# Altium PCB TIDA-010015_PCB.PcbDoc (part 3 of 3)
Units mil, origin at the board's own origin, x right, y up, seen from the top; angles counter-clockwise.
Board outline 6299.21 x 3149.61 mil, 2 copper layers (Top Layer, Bottom Layer), stack 64.6 mil thick; 232 components, 110 nets, 524 pads, 83 vias.
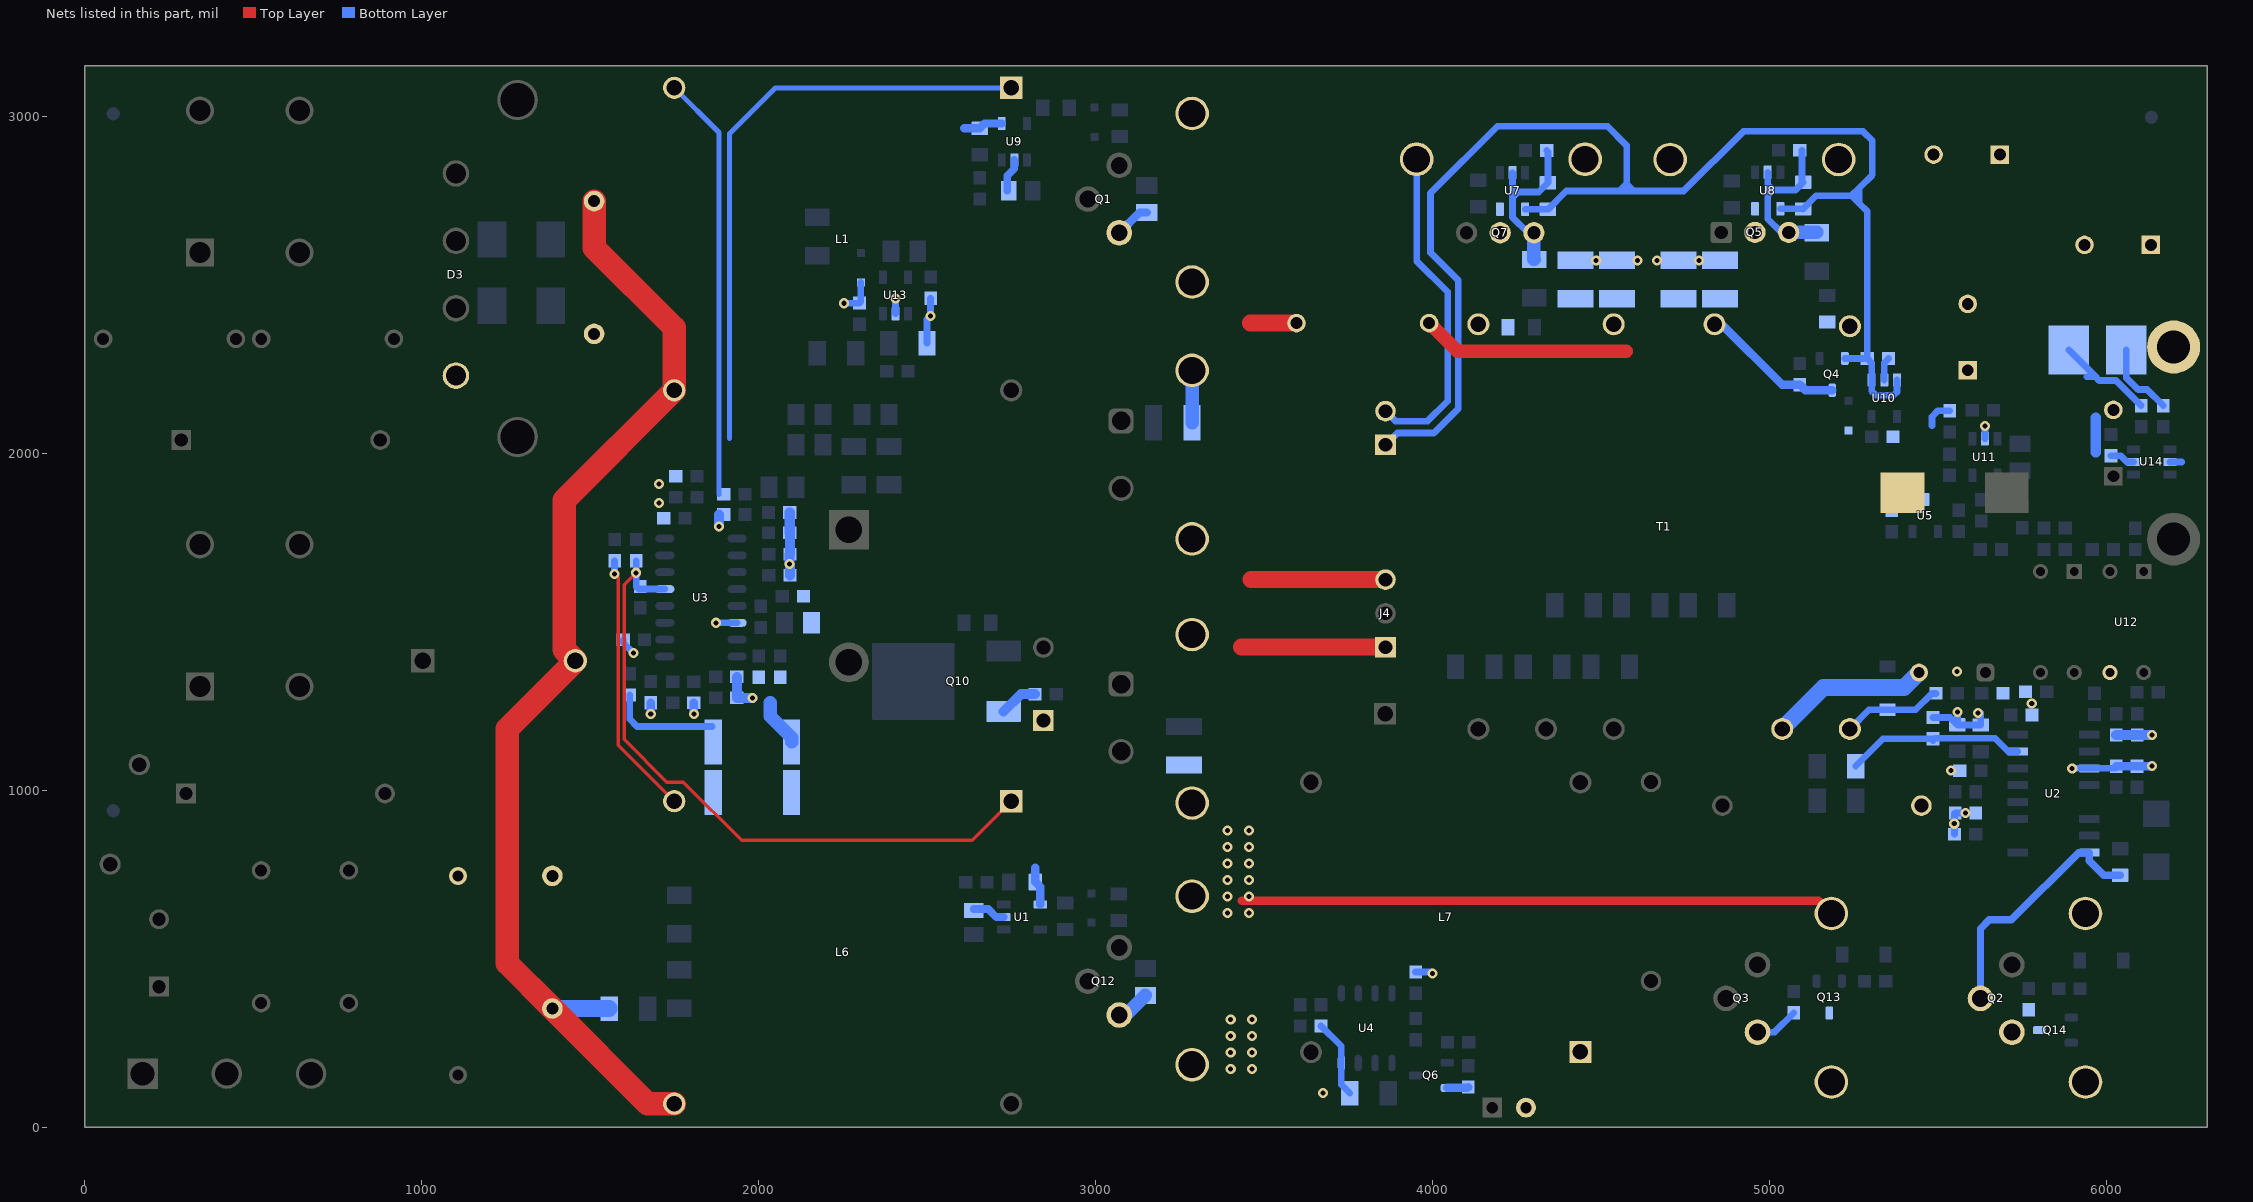
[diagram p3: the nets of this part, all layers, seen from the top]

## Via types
v1: diameter 30, hole 15, Top Layer to Bottom Layer, 83 vias

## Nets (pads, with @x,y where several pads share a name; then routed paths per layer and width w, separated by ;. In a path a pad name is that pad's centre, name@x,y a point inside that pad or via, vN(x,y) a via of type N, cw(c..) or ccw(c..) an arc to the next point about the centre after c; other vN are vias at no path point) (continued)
PGND: C3.2 C7.2 C8.2 C15.1 C16.2 C17.2 C18.2 C19.2 C20.2 C21.2 C22.2 C23.2 C24.2 C25.2 C27.2 C28.2 C29.2 C30.1 C31.2 C32.2 C33.2 C34.2 C35.1 C36.2 C37.2 C38.2 C41.2 C43.2 C51.2 C52.2 C58.2 C59.2 C60.2 C65.2 D20.2 J2.2 J4.1 J4.3 L1.1 L6.1 M1.1 M1.2 M2.1 M2.2 M3.1 M3.2 M4.1 M4.2 M5.1 M5.2 M6.1 M6.2 Q1.3 Q2.3 Q6.2 Q10.3 Q12.3 Q14.3 R1.1 R2.1 R3.1 R6.1 R7.1 R8.1 R11.2 R12.1 R14.2 R19.1 R32.1 R35.1 R41.2 R45.1 R55.1 R64.1 R76.1 R88.2 R89.1 R90.1 RF1.1 T1.5 U1.2 U1.4 U2.11 U3.6 U3.13 U4.4 U9.2 U9.4 U12.3 U13.2 | length 9882.2
  Top Layer w10: v1(1636.71,1645) 1601,1609.29 1601,1151 1728.02,1023.98 1777.02,1023.98 1950,851 2633.43,851 L6.1@2749.63,967.2
  Top Layer w25: 3434.29,671.29 5146.01,671.29 M2.1@5183.31,634
  Top Layer w50: 3432.66,1424.66 J4.1@3860.25,1424.66 ; 3459,2386 C8.2@3596.15,2386 ; 3461.66,1624.66 J4.3@3860.25,1624.66
  Bottom Layer w15: 1914.3,2043.3 1914.3,2948.3 2050.2,3084.2 L1.1@2749.63,3084.2
  Bottom Layer w20: C29.2@1598.5,1446 1598.5,1437.5 v1(1629,1407) ; C24.2@1636.79,1680.78 1636.71,1680.7 v1(1636.71,1645) 1636.71,1604.5 1644.5,1596.7 U3.13@1721.71,1596.7 ; v1(1873.99,1496.7) U3.6@1936.28,1496.7 ; v1(2253,2444.91) 2298.97,2444.91 C28.2@2299.42,2445.36 2303.42,2449.36 D20.2@2303.42,2506.69 ; U13.2@2406.42,2413.87 v1(2406.42,2459.5) ; R76.1@2500.09,2325.91 2500.09,2397.17 v1(2510.42,2407.5) C27.2@2510.42,2459.5 ; R55.1@3669,300.5 3729.36,240.14 U4.4@3729.36,190.49 3729.36,125.75 C51.2@3754.28,100.84 ; C52.2@3949.49,460.18 3995.82,460.18 v1(4000,456) ; C22.2@5485,1215.5 5535.74,1215.5 C19.2@5557.41,1193.83 ; C16.2@5548.5,869 5548.5,930.54 C17.2@5550.47,932.5 v1(5581.91,932.5) ; v1(5557.69,1232) 5557.41,1231.72 C19.2@5557.41,1193.83 ; v1(5619,1229) 5626.16,1229 5626.41,1228.75 R3.1@5626.41,1193.1 5558.13,1193.1 C19.2@5557.41,1193.83 ; v1(5898,1064.85) U2.11@5948.77,1064.85 6026.06,1064.85 C32.2@6032.56,1071.34
  Bottom Layer w23: C23.2@2638.66,647.4 2681.66,647.4 2705.66,623.4 U1.2@2727.73,623.4 ; C15.1@2738,2779 2738,2823 2759,2844 U9.2@2759,2869.87
  Bottom Layer w25: v1(1680,1225.67) C37.2@1679.99,1259.51 ; v1(1808,1225.66) R11.2@1807.99,1259.5 ; 2609.85,2963.85 C59.2@2656,2963.85 2670.28,2978.13 U9.4@2721.6,2978.13 ; 2821.24,769.4 C58.2@2821.24,727.4 2836,712.64 U1.4@2836,660.8 ; Q1.3@3070.17,2654.01 3130.23,2714.07 R6.1@3152,2714.07 ; Q6.2@4043.76,116.39 4103.39,116.39 R64.1@4106,119 ; C32.2@6028.47,1071.34 6032.56,1071.34 v1(6134.47,1071.34)
  Bottom Layer w30: v1(1882.5,1781.99) C25.2@1882.5,1818 ; R88.2@1935.51,1336 C41.2@1935.51,1274 v1(1981.88,1274) ; R35.1@2092.44,1824.04 C33.2@2092.44,1764.04 2092.99,1763.48 R89.1@2092.99,1700.5 2092,1699.51 v1(2092,1671) 2092.99,1670.01 C21.2@2092.99,1637.5 ; Q10.3@2726.86,1233.24 2778.62,1285 R14.2@2820.5,1285 ; R32.1@6028.47,1163.85 C31.2@6090.47,1163.85 6133.97,1163.85 v1(6134.47,1163.34)
  Bottom Layer w40: 2035,1260 2035,1219 2098,1156 R7.1@2098,1143.24 ; Q12.3@3070.17,332.93 3089.93,332.93 R19.1@3148,391 ; C7.2@3286.09,2090 3286.47,2090.39 M6.1@3286.47,2245.72
  Bottom Layer w50: T1.5@5037.39,1181.61 5160.29,1304.5 5399.08,1304.5 C60.2@5443.57,1349
  other v1: 3675,101 3401,172.3 3464,172.3 3401,221.3 3464,221.3 3401,270.3 3464,270.3 3401,319.3 3464,319.3 3392,635 3455,635 3392,684 3455,684 3392,733 3455,733 3392,782 3455,782 3392,831 3455,831 3392,880 3455,880 5547.91,900.5 5537.94,1058 5778,1257 5556,1352 1704,1852 1704,1908.16
R_SENSE: pad.1@6199,2315 R65.2 R66.1 | length 226.1
  Bottom Layer w20: R65.2@6058.04,2306 6058.04,2224.64 6093.68,2189 6120.3,2189 R66.1@6168.2,2141.09
SGND: C12.2 C13.2 C14.2 C44.1 C45.1 C46.2 C48.2 C53.2 C54.2 C55.2 C56.2 C57.2 C67.2 C68.2 C72.2 C73.2 C76.2 D4.2 J5.2 M7.1 M7.2 M8.1 M8.2 Q5.3 Q7.3 R50.1 R65.1 R72.1 R78.1 U5.3 U7.2 U8.2 U10.2 U11.2 U14.2 U14.5 | length 2810.5
  Top Layer w20: v1@5638.87,2081 v1(5639,2080.87)
  Bottom Layer w20: J5.2@3860.25,2124.66 3889.91,2095 3984.87,2095 4045,2155.13 4045,2478 3952.86,2570.14 M7.1@3952.86,2872.1 ; U7.2@4237.32,2832.11 4237.32,2792.68 ; Q7.3@4300.7,2654.06 4282.94,2654.06 4237.32,2699.68 4237.32,2758 ; C53.2@4338.81,2897.97 4342.32,2894.47 C46.2@4342.32,2802.34 4314.97,2775 4255,2775 ; U8.2@4994.39,2833.36 4994.39,2798 ; Q5.3@5056.7,2655.06 5034.94,2655.06 4994.39,2695.61 4994.39,2763.72 ; C54.2@5095.88,2899.22 5095.88,2807.1 C48.2@5099.39,2803.59 5076.65,2780.86 5011.53,2780.86 ; U10.2@5340.44,2217.02 5340.44,2268.32 C55.2@5353,2280.89 ; 5482,2081 5482,2108.16 5499.92,2126.08 R72.1@5535,2126.08 ; v1(5639,2080.87) 5639.07,2080.8 U11.2@5639.07,2042.63 ; R65.1@5887.96,2306 5966.98,2226.98 ; 5940.98,2226.98 5966.98,2226.98 ; C57.2@6013,1992.5 6041.5,1992.5 6060,1974 U14.5@6079.73,1974 ; R78.1@6102.41,2141.09 6027.65,2215.86 5978.1,2215.86 5966.98,2226.98 ; U14.2@6188,1974 6188.4,1973.6 6223.39,1973.6 ; 4237.32,2758 4237.32,2775 ; 4237.32,2758 4254.32,2775 ; 4237.32,2775 4254.32,2775 ; 4237.32,2775 4237.32,2792.68 ; 4237.32,2792.68 4255,2775 ; 4254.32,2775 4255,2775 ; 4994.39,2763.72 4994.39,2780.86 ; 4994.39,2763.72 5011.53,2780.86 ; 4994.39,2780.86 5011.53,2780.86 ; 4994.39,2780.86 4994.39,2798 ; 4994.39,2798 5011.53,2780.86
  Bottom Layer w30: 5968,2002 5968,2105
  Bottom Layer w40: Q7.3@4300.7,2654.06 4300.7,2575.76 C45.1@4301.45,2575 ; Q5.3@5056.7,2655.06 C44.1@5139.97,2655.06
  other v1: 4485.5,2572.09 4608,2572 4666,2572 4790,2572.09
SW: C26.2 L7.1 Q2.2 Q3.3 Q13.3 R44.1 U2.16 | length 888.7
  Bottom Layer w20: Q3.3@4964,282 5014.5,282 R44.1@5072,339.5
  Bottom Layer w22: Q2.2@5625.83,382.07 5625.83,589.13 5652,615.3 5717.35,615.3 5916.9,814.85 U2.16@5948.77,814.85 5948.77,790.38 5991.52,747.63 C26.2@6040,747.63
V24V: C8.1 C12.1 C13.1 C14.1 C67.1 C68.1 C72.1 C73.1 L4.1 Q4.3 R62.2 T1.8 T1.9 | length 1049.4
  Top Layer w40: C8.1@3989.85,2386 4073.85,2302 4574,2302
  Bottom Layer w25: T1.8@4836.61,2382.39 4857.61,2382.39 5036.8,2203.2 R62.2@5090,2203.2 5106.45,2186.76 Q4.3@5186,2186.76
VAC: C5.1 C61.1 L1.3 L2.2 L6.3 R23.2 | length 3430.2
  Top Layer w70: C61.1@1512,2747.85 1512,2609.72 1749.63,2372.09 L1.3@1749.63,2186.56 1423,1859.93 1423,1417.38 L2.2@1456.38,1384 1254,1181.62 1254,486.15 C5.1@1388,352.15 1670.59,69.56 L6.3@1749.63,69.56
  Bottom Layer w50: C5.1@1388,352.15 1388.15,352 R23.2@1556.91,352
VCR: C22.1 C40.2 U2.7 | length 533.5
  Bottom Layer w20: C40.2@5255.37,1071 5336.87,1152.5 C22.1@5485,1152.5 ; C22.1@5485,1147.5 5491.5,1154 5668.96,1154 5708.11,1114.85 U2.7@5736.17,1114.85
VD1: Q7.2 R53.1 T1.10 U7.5
VD2: Q5.2 R52.1 T1.7 U8.5
VDD: C46.1 C48.1 C55.1 J5.1 Q4.2 U7.4 U8.4 U10.1 U10.3 | length 4219.1
  Bottom Layer w20: J5.1@3860.25,2024.66 3895.59,2060 4003.82,2060 4076.44,2132.62 4076.44,2512.56 3994,2595 3994,2771.51 4192.49,2970 4519,2970 4576,2913 4576,2799 ; U7.4@4274.72,2723.84 4274.95,2723.6 C46.1@4342.32,2723.6 4396.71,2778 4555,2778 ; 4607,2778 4597,2778 ; U8.4@5031.79,2725.09 5099.15,2725.09 C48.1@5099.39,2724.85 5138.54,2764 5243,2764 ; Q4.2@5223.4,2281.24 5223.76,2280.89 C55.1@5290.01,2280.89 ; 5267.91,2788.91 5266,2787 ; U10.3@5377.84,2217.02 5377.84,2181.67 5368.09,2171.92 5316.09,2171.92 5303.03,2184.97 U10.1@5303.03,2217.02 5303.03,2267.86 C55.1@5290.01,2280.89 ; 4555,2778 4576,2799 ; 4555,2778 4576,2778 ; 4576,2778 4576,2799 ; 4576,2778 4597,2778 ; 4576,2799 4597,2778 ; 4597,2778 4745,2778 4922,2955 5277,2955 5305,2927 5305,2826 5266,2787 ; 5243,2764 5266,2741 ; 5243,2764 5266,2787 ; 5266,2741 5290.01,2716.99 C55.1@5290.01,2280.89 ; 5266,2741 5266,2787
VN: C4.2 C5.2 C61.2 D3.4 R7.2 R8.2 R30.1 | length 324.9
  Bottom Layer w20: R30.1@1618,1282.5 1618,1210.49 1639.49,1189 R7.2@1862,1189
X: D11.2 R9.2 T1.6 | length 299
  Bottom Layer w20: T1.6@5238.18,1181.61 5295.11,1238.53 D11.2@5350,1238.53 5433.53,1238.53 5482,1287 R9.2@5493.5,1287
ZCD1: L1.2 R26.2 | length 1261.2
  Bottom Layer w15: L1.2@1749.63,3084.2 1882.5,2951.33 R26.2@1882.5,1878
ZCD2: L6.2 R24.1 | length 786.7
  Top Layer w10: v1@1572.3,1641.3 1583.3,1630.3 1583.3,1133.53 L6.2@1749.63,967.2
  Bottom Layer w20: v1(1572.68,1641.68) R24.1@1572.68,1680.78
pads on no net: FID1.1 FID2.1 FID3.1 H1.0 H2.0 H3.0 H4.0 H5.0 H6.0 H7.1 H7.2 L7.4 T1.2 U4.2 U4.5 U4.6 U10.4

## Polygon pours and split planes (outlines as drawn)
24V on Top Layer "24V_L01_P164" (solid, remove dead copper, pour order 164): 6257.2,1964.8 5654.22,1964.8 5632,1942.57 5632,1691 5678,1645 6244,1645 6292,1693 6292,1930
V24V on Top Layer "V24V_L01_P158" (solid, remove dead copper, pour order 158): 4540,2440 4502,2402 4502,1946 4517.5,1929.5 4617.5,1829.5 4650,1798 5442,1798 5469.83,1825.83 5469.83,2006.83 5598,2135 5951,2135 6269,2453 6269,3044 6195,3118 5634,3118 5614,3098 5614,2891 5789,2716 5982,2716 6019,2679 6019,2514 5835,2330 4972,2330 4862,2440
SGND on Top Layer "SGND_L01_P156" (solid, remove dead copper, pour order 156): 5931,2673 5964,2640 5964,2512 5934,2482 5834,2382 5153,2382 5053,2482 3927,2482 3855,2554 3855,2899 3855,3075 3910,3130 5531,3130 5567,3094 5567,2862 5756,2673
PGND on Top Layer "PGND_L01_P132" (solid, remove dead copper, pour order 132): 5421.39,1373 5406.39,1358 5406.39,1047.39 5347,988 5347,939 5366,920 5507,920 5601,826 5877,826 6031,672 6031,111 6102.43,39.57 6277.57,39.57 6297,59 6297,1323 6247,1373
NetC6_1 on Top Layer "NETC6_1_L01_P002" (solid, remove dead copper, pour order 2): 398,1348 384,1362 295,1362 278,1345 278,1049 35,806 35,695 148,582 416,582 556,722 556,880 398,1038
NetF1_1 on Top Layer "NETF1_1_L01_P000" (solid, remove dead copper, pour order 0): 105,441.1 105,107 125,87 243,87 273,117 273,443 250,466 130.1,466
PGND on Top Layer "PGND_L01_P102" (solid, remove dead copper, pour order 102): 5466,988 5484,970 5484,917 5602.92,798.08 5853.85,798.08 5894.31,758.23 5996,656.54 5996,94 5907,5 5130.72,5 5084,54.24 5084,535 5043,576 4365,576 3789,0 3061,0 3041,20 3041,331 3077,367 3193,367 3227,401 3227,994 3251,1018 3251,1391 3158,1484 3158,1738 3228,1808 3228,2404.48 3031,2601.48 3031,2669 3052,2690 3176,2690 3211,2725 3211,3151 3530,3151.8 3530,2638 3530,896 3561.79,863 5222,863 5347,988
PGND on Top Layer "PGND_L01_P114" (solid, remove dead copper, pour order 114): 2159,2480 2497,2480 2536,2441 2536,2373 2137,1974 2137,1309 2005.87,1177.87 1639.13,1177.87 1614,1203 1614,1819 1614,1935
SGND on Bottom Layer "SGND_L02_P166" (solid, remove dead copper, pour order 166): 6269.24,1745 6296,1771.76 6296,1976.72 6256.72,2016 6157,2016 5863,2016 5673,2206 5498.32,2206 5426,2278.32 5400.32,2304 5247,2304 5246,2303 5218,2275 5218,1858 5331,1745
SGND on Bottom Layer "SGND_L02_P162" (solid, remove dead copper, pour order 162): 5951,2436 6004,2489 6004,3065 5971,3098 5487,3098 5452,3063 5453,3062 5453,2893 5453,2479 5849,2083 6027.61,2083 6054,2109.39 6054,2157 6020.73,2190.27 5959.73,2190.27 5951,2199 5951,2335
V24V on Bottom Layer "V24V_L02_P160" (solid, remove dead copper, pour order 160): 4359.67,2480 4359.67,2361.33 4375,2345 4892,2345 4901,2354 4901,2478 4893.67,2485.33 4365,2485.33
PGND on Bottom Layer "PGND_L02_P140" (solid, remove dead copper, pour order 140): 3225,216 3510,501 4171,501 4307,365 4307,45 4284,22 3248,22 3225,45
PGND on Bottom Layer "PGND_L02_P138" (solid, remove dead copper, pour order 138): 5499.65,914.35 5535,879 5588,879 5638,929 5764,929 5867,1032 6225,1032 6278,1085 6278,1344 6250,1372 5513.3,1372 5499.65,1358.35
NetC2_2 on Bottom Layer "NETC2_2_L02_P136" (solid, remove dead copper, pour order 136): 4502,1118 4502,1206 4519,1223 4590,1223 4808,1005 4885,1005 4893,997 4893,939 4876,922 4698,922
NetL7_2 on Bottom Layer "NETL7_2_L02_P134" (solid, remove dead copper, pour order 134): 4307.86,1078.71 4166.58,1220 4111.33,1220 4099,1207.67 4099,1036.5 4177,961 4443,961 4472,990 4472,1048 4441.29,1078.71
PGND on Bottom Layer "PGND_L02_P130" (solid, remove dead copper, pour order 130): 5686,295 5686,250 5706,230 5794.44,230 5820.44,256 5820.44,357.56 5809,369 5753,369 5686,302
NetC28_1 on Bottom Layer "NETC28_1_L02_P084" (solid, remove dead copper, pour order 84): 2354,2433.91 2354,2410.91 2345,2401.91 2267,2401.91 2258,2392.91 2258,2240.91 2278,2220.91 2401,2220.91 2412,2231.91 2412,2349.91 2382,2379.91 2382,2432.91 2379,2435.91 2356,2435.91
390V on Bottom Layer "390V_L02_P050" (solid, pour order 50): 3373.53,1166.45 3189.55,1166.45 3133,1223 3089,1223 3009,1303 3009,1398 2726.22,1680.78 2228.22,1680.78 2204,1705 2204,1915 2220,1931 2665,1931 2879,2145 3194.33,2145 3197.33,2142 3197.33,2038.33 3194,2035 3008,2035 2870.85,1897.85 2870.85,1717.15 3255,1333 3548.38,1333 4043.38,838 4468,838 4905,401 4905,363 4873,331 4639,331 4392.76,577.24 3962.25,577.77
VN on Bottom Layer "VN_L02_P104" (solid, remove dead copper, pour order 104): 1361,1293.91 1493.29,1161.61 1822.61,1161.61 1834.67,1173.67 1834.67,1207.67 1844,1217 1890,1217 1896,1211 1896,927 1890,921 1821,921 1810,932 1810,1021 1785,1046 1599.38,1046 1556,1001.62 1556,754 1495.31,693.31 1100,693.31 1076.19,717.12 1076.19,798.04 1100,821.85 1100,1750 1366,2016 1366,2122 1339,2151 1063,2151 1051,2163 1051,2251 1076.19,2276.19 1437.69,2276.19 1485.51,2324 1485.51,2380.51 1499,2394 1555,2394 1567.98,2381.02 1567.98,1997.98 1361,1791
PGND on Bottom Layer "PGND_L02_P106" (solid, remove dead copper, pour order 106): 2186,1580 2186,1468 2145,1427 2145,1262 2124,1240 1667,1240 1657,1250 1657,1343 1580,1420 1580,1920.79 1730.2,2071 2059,2071 2122,2008 2122,1644
PGND on Bottom Layer "PGND_L02_P110" (solid, remove dead copper, pour order 110): 3321,1093 3237,1093 3163,1019 3005,1019 2881,1143 2881,1239 2875,1245 2795,1245 2762,1278 2676,1278 2661,1263 2661,1204 2602.03,1145.03 2204.97,1145.03 2139,1211 2069,1211 2063,1205 2063,905 2137,831 3008,831 3205,634 3244,595 3446.03,595 3495,643.97 3495,919
NetC1_2 on Bottom Layer "NETC1_2_L02_P112" (solid, remove dead copper, pour order 112): 2208,1408 2208,1251 2249,1210 2573,1210 2583,1220 2583,1431 2566,1448 2248,1448
PGND on Bottom Layer "PGND_L02_P116" (solid, remove dead copper, pour order 116): 2578,2764.5 2780.5,2562 3157,2562 3189,2594 3189,2734 3184,2739 3106,2739 3016,2649 2868.26,2649 2843.26,2674 2843.26,2972.24 2805.5,3010 2610,3010 2578,2978
PGND on Bottom Layer "PGND_L02_P118" (solid, remove dead copper, pour order 118): 2690.59,218.77 2566.13,343.23 2566.13,759.47 2598.66,794 2860,794 2875,779 2875,373 2918,330 3017,330 3102,415 3179,415 3187,407 3187,352 3053.77,218.77
SW on Bottom Layer "SW_L02_P128" (solid, remove dead copper, pour order 128): 4893.52,261.61 4402.61,261.61 4389,248 4389,162 4408,143 4929.93,143 4980.97,193.97 5018.27,231.27 5413.27,231.27 5525,343 5637,343 5659,365 5659,397.18 5637.18,419 5468.87,419 5407.42,357.56 4989.46,357.56 4945.9,314
VD1 on Bottom Layer "Bottom Layer-No Net 1" (solid, remove dead copper, pour order 172): 4186,2684 4168,2666 4168,2633 4103,2568 4103,2354 4115,2342 4239,2342 4245,2348 4245,2605 4232,2618 4232,2678.33 4213,2697.33 4213,2742 4210,2745 4188,2745 4186,2743
VD2 on Bottom Layer "Bottom Layer-No Net" (solid, remove dead copper, pour order 174): 4942,2686 4925,2669 4925,2387.9 4969.9,2343 5253,2343 5271,2361 5271,2408 5251,2428 5250,2427 5155,2427 4989,2593 4989,2666.33 4970,2685.33 4970,2747 4967,2750 4944.25,2750 4942,2747.75
R_SENSE on Bottom Layer "Bottom Layer-No Net 2" (solid, remove dead copper, pour order 176): 5995,2238 5999,2234 6254.75,2234 6277.75,2257 6277.75,2406.25 6252,2432 6010,2432 5995,2417
SGND on Bottom Layer "Bottom Layer-No Net 3" (solid, remove dead copper, pour order 178): 4368,2600 4368,2547 4373,2542 4903,2542 4909,2548 4909,2597 4904,2602 4370,2602

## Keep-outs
Keep-Out Layer:
  text ".Layer_Name" at 441.88,-892.69 h60

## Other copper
Top Layer:
  pour cut-out: 5595.49,456.25 5581.78,448.93 5569.77,439.07 5559.91,427.05 5552.58,413.34 5548.07,398.47 5546.54,383 5548.07,367.53 5552.58,352.66 5559.91,338.95 5569.77,326.93 5581.78,317.07 5595.49,309.75 5610.37,305.23 5625.83,303.71 5641.3,305.23 5655.2,309 5669.89,317.07 5681.9,326.93 5691.76,338.95 5699.09,352.66 5703.6,367.53 5705.12,383 5703.6,398.47 5699.09,413.34 5690.16,429 5675.43,445 5667.96,449.96 5653.87,456.95 5641.3,460.77 5625.83,462.29 5610.37,460.77
  text ".Layer_Name" at 441.88,-892.69 h60
Bottom Layer:
  pour cut-out: 2697.69,921.9 2703.59,916 2794,916 2804,926 2804,1011 2796,1019 2706,1019 2697.69,1010.69
  text ".Layer_Name" at 441.88,-892.69 h60

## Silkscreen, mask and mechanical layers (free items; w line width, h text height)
Top Overlay:
  text "SGND" at 6289,2373 h30 r90
  text "24V/20A" at 6280,1474 h30 r90
  text "300V/10A" at 42.5,378.79 h30 r90
  text "E" at 625.66,325 h40
  text "L" at 85,324 h40
  text "N" at 362.58,324 h40
  text "230V/6A" at 837.21,28 h35
  text ".Layer_Name" at 441.88,-892.69 h60
Bottom Overlay:
  lines w6: 1742,1223 1742,1188 ; 1795,2100 1810.5,2084.5 1810.5,1980 ; 1900,1913 1900,1942 ; 1963.99,1246.73 1978.36,1232.37 2159,1232.37 ; 2007,1295 2024,1278 2036,1278 ; 2102.24,1440 2195,1440 2204,1449 2204,1618 2150,1672 2150,1819 2130,1839 ; 2335,1607 2219,1607 ; 2346,2541 2346,2659 ; 2346,2568 2346,2536 2350,2532 ; 5520.02,1111 5442,1111 ; 5655.42,1889.98 5669.39,1903.94 5834,1903.94 ; 5683.58,2074 5692.58,2083 5734,2083 ; 5716,2102 5716,2111 ; 5849,1676 5849,1627 ; 6126,1196.36 6175,1196.36 ; 6127,1037 6170,1037 6176,1037 ; 1742,1188 1749,1195 1734.89,1195 1741.89,1188 1742,1188 ; 1810.5,1980 1819,1988.5 1801.5,1988.5 1810,1980 1810.5,1980 ; 1900,1942 1907,1935 1893,1935 1900,1942 ; 2219,1607 2228,1616 2228,1598 2219,1607 ; 5442,1111 5448,1117 5448,1105 5442,1111 ; 5834,1903.94 5826.37,1911.57 5826.37,1896.37 5833.94,1903.94 5834,1903.94 ; 5849,1627 5857,1635 5841.72,1635 5849,1627.72 5849,1627 ; 6175,1196.36 6166,1205.36 6166,1187.7 6174.66,1196.36 6175,1196.36 ; 6176,1037 6168,1045 6168,1029 6176,1037 ; 2342,1517.36 2351.36,1508 2488.06,1508 2498,1517.94 2498,1754 2489,1763 2476,1776 2377,1776 2342,1741 2342,1517.36
  text "TIDA-010015-E1" at 6253,2702.06 h70
  text "SGND" at 6207,2407 h40 r270
  text "24V/20A" at 6234,1393 h40 r270
  text ".Layer_Name" at 441.88,-892.69 h60
Top Paste:
  text ".Layer_Name" at 441.88,-892.69 h60
Bottom Paste:
  text ".Layer_Name" at 441.88,-892.69 h60
Top Solder:
  text ".Layer_Name" at 441.88,-892.69 h60
  text ".Layer_Name" at 441.88,-892.69 h60
Bottom Solder:
  text ".Layer_Name" at 441.88,-892.69 h60
Drill Guide:
  text ".Layer_Name" at 441.88,-892.69 h60
M1 Board Outline:
  the board outline again, w6
M2 Board Dimensions:
  rectangle: -135.12,-309.2 -10.12,-184.2
  rectangle: -10.12,-434.2 364.88,-309.2
  lines w7: -135.12,-309.2 864.88,-309.2 ; -10.12,-434.2 -10.12,-184.2 ; 114.88,-434.2 114.88,-184.2 ; 364.88,-434.2 364.88,-184.2 ; 614.88,-434.2 614.88,-184.2 ; -135.12,-434.2 864.88,-434.2 864.88,-184.2 -135.12,-184.2 -135.12,-434.2
M3 3D STEP Top:
  text ".Layer_Name" at 441.88,-892.69 h60
M4 3D STEP Bottom:
  text ".Layer_Name" at 441.88,-892.69 h60
M5 Assembly Top:
  lines w10: -427.12,-964.37 6172.88,-964.37 ; -427.12,-761.03 6174.88,-761.03 ; -427.12,-557.7 -427.12,-1167.7 3577.88,-1167.7 6174.88,-1167.7 6174.88,-557.7 -426.62,-557.7 -426.62,-1167.7 1148.88,-1167.7 ; 2037.88,-1167.7 2037.88,-557.7 ; 3304.88,-761.03 3304.88,-557.7 ; 4144.88,-761.03 4144.88,-557.7 ; 4766.88,-1174.2 4766.88,-971.37
  text "COMPONENTS MARKED 'DNP' SHOULD NOT BE POPULATED." at 1018.38,-352.7 h60
  text "ASSEMBLY VARIANT:" at 1017.88,-468.2 h60
  text ".VariantName" at 2053.88,-468.2 h60
  text "PCB VIEWED FROM TOP SIDE" at -363.62,-689.87 h60
  text "BOARD #:" at 2112.88,-689.87 h60
  text ".PRJ_Number" at 2658.38,-689.87 h60
  text "REV:" at 3502.88,-689.87 h60
  text ".PCB_Rev" at 3794.38,-689.87 h60
  text "SVN REV:" at 4340.88,-689.87 h60
  text ".VersionControl_RevNumber" at 4846.88,-689.87 h60
  text "LAYER NAME =" at -363.62,-892.69 h60
  text "TID #:" at 2112.88,-893.2 h60
  text ".TID" at 2658.38,-893.2 h60
  text ".layer_Name" at 432.88,-895.2 h60
  text "PLOT NAME =" at -363.62,-1098.54 h60
  text ".plot_File_Name" at 441.88,-1098.54 h60
  text "GENERATED    :" at 2114.88,-1098.54 h60
  text ".Print_Date" at 2984.38,-1098.54 h60
  text ".Print_Time" at 3713.38,-1098.54 h60
  text "TEXAS INSTRUMENTS" at 4977.88,-1098.54 h60
M6 Assembly Bottom:
  lines w10: -427.62,-761.53 6174.38,-761.53 ; -425.62,-964.87 6174.38,-964.87 ; 980.38,-1174.7 980.38,-971.87 ; 1602.38,-761.53 1602.38,-558.2 ; 2442.38,-761.53 2442.38,-558.2 ; 3709.38,-1168.2 3709.38,-558.2 ; 4598.38,-1168.2 6173.88,-1168.2 6173.88,-558.2 -427.62,-558.2 -427.62,-1168.2 2169.38,-1168.2 6174.38,-1168.2 6174.38,-558.2
  text "COMPONENTS MARKED 'DNP' SHOULD NOT BE POPULATED." at 5966.88,-352.2 h60
  text ".VariantName" at 4922.88,-468.2 h60
  text "ASSEMBLY VARIANT:" at 5961.88,-468.2 h60
  text ".VersionControl_RevNumber" at 900.38,-690.37 h60
  text "SVN REV:" at 1406.38,-690.37 h60
  text ".PCB_Rev" at 1952.88,-690.37 h60
  text "REV:" at 2244.38,-690.37 h60
  text ".PRJ_Number" at 3088.88,-690.37 h60
  text "BOARD #:" at 3634.38,-690.37 h60
  text "PCB VIEWED FROM BOTTOM SIDE" at 6110.88,-690.37 h60
  text "LAYER NAME =" at 6110.88,-886.6 h60
  text ".TID" at 3088.88,-893.7 h60
  text "TID #:" at 3634.38,-893.7 h60
  text ".layer_Name" at 5288.88,-895.2 h60
  text "TEXAS INSTRUMENTS" at 769.38,-1099.04 h60
  text ".Print_Time" at 2033.88,-1099.04 h60
  text ".Print_Date" at 2762.88,-1099.04 h60
  text "GENERATED    :" at 3632.38,-1099.04 h60
  text ".plot_File_Name" at 5305.38,-1099.04 h60
  text "PLOT NAME =" at 6110.88,-1099.04 h60
M9 Title Sheet:
  drawing of 57 lines, arcs and shapes, not listed
  text "1" at 604.72,8002.3 h70
  text "2" at 3100.38,8002.3 h70
  text "3" at 5589.72,8002.3 h70
  text "4" at 8096.39,8002.3 h70
  text "5" at 10595.38,8002.3 h70
  text "6" at 13100.38,8002.3 h70
  text "A" at -551.62,6859.3 h70
  text "A" at 14248.38,6859.3 h70
  text "B" at -551.62,4479.3 h70
  text "B" at 14248.38,4479.3 h70
  text "C" at -551.62,2104.3 h70
  text "C" at 14248.38,2104.3 h70
  text "PROJECT TITLE:" at 11208.38,243.3 h45
  text ".PRJ_Title" at 11258.38,109.97 h60
  text "DESIGNED FOR:" at 11208.38,-57.7 h45
  text ".PRJ_Customer" at 11258.38,-197.7 h70
  text "D" at -551.62,-265.7 h70
  text "D" at 14248.38,-265.7 h70
  text "FILE NAME:" at 11208.38,-357.7 h45
  text ".PCB_File_Name_No_Path" at 11258.38,-477.7 h70
  text "Texas Instruments (TI) and/or its licensors do not warrant the accuracy or completeness of this specification" at 6238.88,-639.54 h45
  text "ENGINEER:" at 11208.38,-647.7 h45
  text "LAYOUT BY:" at 12713.38,-647.7 h45
  text "or any information contained therein. TI and/or its licensors do not warrant that this design will meet" at 6193.89,-752.2 h45
  text ".PRJ_Engineer" at 11258.38,-802.69 h70
  text ".PCB_Layout" at 12763.88,-802.69 h70
  text "the specifications, will be suitable for your application or fit for any particular purpose, or will operate in" at 6193.89,-864.87 h45
  text "ALTIUM DESIGNER VERSION:" at 12713.38,-957.7 h45
  text "an implementation. TI and/or its licensors do not warrant that the design is production worthy. You should" at 6193.89,-977.53 h45
  text "completely validate and test your design implementation to confirm the system functionality for your application." at 6238.88,-1090.2 h45
  text ".print_Scale" at 11258.38,-1091.03 h70
  text ".Application_BuildNumber" at 12763.88,-1091.03 h70
  text "1" at 604.72,-1297.7 h70
  text "2" at 3100.38,-1297.7 h70
  text "3" at 5589.72,-1297.7 h70
  text "4" at 8096.39,-1297.7 h70
  text "5" at 10595.38,-1297.7 h70
  text "6" at 13100.38,-1297.7 h70
M10 Fab Notes:
  drawing of 191 lines, arcs and shapes, not listed
  text "DESIGN INFORMATION" at 12251.9,6651.8 h60
  text "(REFER ALSO ARRAY/PANEL PROFILING INFORMATION)" at 11890.34,6490.09 h60
  text "BOARD SIZE" at 11204.34,6485.8 h60
  text "X" at 12172.34,6357.98 h60
  text "80MM" at 12407.88,6350.8 h60
  text "160MM" at 11720.38,6347.31 h60
  text "Number of Layers :" at 11622.34,6250.8 h60
  text "2" at 12717.15,6240.8 h60
  text "MIN. TRACK WIDTH:" at 11622.34,6111.8 h60
  text "10" at 12691.88,6112.2 h60
  text "MIL" at 12873.34,6111.8 h60
  text "MIN. CLEARANCE:" at 11622.34,5979.8 h60
  text "7.7" at 12640.38,5979.31 h60
  text "MIL" at 12890.88,5953.2 h60
  text "30" at 12688.88,5856.81 h60
  text "MIN. VIA PAD SIZE:" at 11622.34,5847.8 h60
  text "MIL" at 12890.88,5825.2 h60
  text "0.15mm (5.91MIL)" at 12317.34,5706.09 h60
  text "EXTERNAL" at 13053.88,5706.2 h60
  text "MINIMUM ANNULAR RING" at 11293.11,5701.81 h60
  text "PER" at 11493.11,5583.8 h60
  text "IPC-D-275 CLASS 2 LEVEL C" at 11713.11,5583.8 h60
  text "MIL, HOLES" at 13201.34,5471.51 h60
  text "+/-" at 12808.88,5470.8 h60
  text "+/-" at 13662.88,5470.8 h60
  text "REGISTRATION TOLERANCES:" at 11293.11,5465.8 h60
  text "METAL" at 12492.88,5465.8 h60
  text "5" at 13069.08,5465.8 h60
  text "3" at 13902.08,5465.8 h60
  text "MIL" at 14018.34,5465.8 h60
  text "IMPEDENCE CONTROLLED BOARD:NO" at 11325.88,5316.8 h60
  text "MATERIAL:" at 11202.34,5093.34 h60
  text "FR-4 High Tg" at 12188.78,4953.01 h60
  text "FR-408" at 11623.34,4944.44 h60
  text "OTHER" at 13111.34,4944.44 h60
  text "X" at 12026.88,4942.8 h60
  text "THICKNESS:" at 11203.88,4787.8 h60
  text "63 MIL (1.6mm) +/-10%" at 11862.88,4782.8 h60
  text "OTHER" at 13228.34,4777.44 h60
  text "X" at 11727.88,4774.8 h60
  text "TOLERANCE:" at 11277.11,4619.44 h60
  text "X" at 12116.41,4619.44 h60
  text "ANSI IPC-6012 TYPE 3 CLASS 2" at 12303.36,4619.44 h60
  text "OTHER +/-" at 12303.34,4463.44 h60
  text "BOW & TWIST:" at 11277.11,4306.44 h60
  text "X" at 12116.41,4306.44 h60
  text "ANSI IPC-6012 TYPE 3 CLASS 2" at 12303.36,4306.44 h60
  text "OTHER +/-" at 12303.34,4147.93 h60
  text "DRILLING:" at 11202.34,4009.44 h60
  text "REFERENCE:" at 11277.11,3892.44 h60
  text "X" at 11925.34,3892.44 h60
  text "AS SHOWN" at 12112.34,3892.44 h60
  text "X" at 12826.34,3892.44 h60
  text "NC_DRILL FILES" at 12963.34,3892.44 h60
  text "PTH MIN COPPER THICKNESS:" at 11277.11,3734.44 h60
  text "X" at 12627.34,3734.44 h60
  text "1MIL" at 12764.34,3734.44 h60
  text "OTHER" at 13261.34,3734.44 h60
  text "BOARD FINISH:" at 11202.34,3575.44 h60
  text "SILKSCREEN:" at 11357.56,3457.44 h60
  text "X" at 12306.34,3457.44 h60
  text "TOP" at 12432.34,3457.44 h60
  text "X" at 12810.34,3457.44 h60
  text "BOTTOM" at 12943.34,3457.44 h60
  text "SILKSCREEN COLOR:" at 11357.56,3290.44 h60
  text "X" at 12305.3,3290.44 h60
  text "WHITE" at 12432.34,3290.44 h60
  text "OTHER" at 12943.34,3290.44 h60
  text "SOLDER RESIST COLOR:" at 11357.56,3120.44 h60
  text "X" at 11925.3,2961.24 h60
  text "GREEN" at 12052.34,2961.24 h60
  text "BLUE" at 12643.34,2961.24 h60
  text "OTHER" at 13181.34,2961.24 h60
  text "IMMERSION GOLD (ENIG)" at 12263.34,2772.72 h60
  text "ENEPIG" at 13600.88,2769.44 h60
  text "SURFACE FINISH:" at 11202.34,2768.44 h60
  text "X" at 12076.39,2768.44 h60
  text "IMM. TIN/SILVER OR EQUIV" at 11531.88,2611.44 h60
  text "OTHER" at 12963.34,2611.44 h60
  text "ARRAY/PANEL:" at 11202.34,2432.44 h60
  text "X" at 12084,2428.88 h60
  text "CUT AND TRIM PER MECH LAYER 1" at 12263.34,2428.15 h60
  text "N.C. ROUTE" at 12263.34,2276.44 h60
  text "V. SCORE" at 13129.34,2276.44 h60
  text "CERTIFICATION:" at 11202.34,2139.44 h60
  text "MATERIALS AND WORKMANSHIP FOR ALL PCBS" at 11927.34,2139.44 h60
  text "TO MEET OR EXCEED THE REQUIREMENTS OF:" at 11927.34,2041.44 h60
  text "X" at 11553.84,1904.94 h60
  text "ANSI IPC-A-600F CLASS ->" at 11692.84,1904.94 h60
  text "X" at 13331.9,1904.94 h60
  text "2" at 13450.84,1904.94 h60
  text "1" at 13135.84,1903.44 h60
  text "3" at 13804.84,1903.44 h60
  text "X" at 11555.9,1745.44 h60
  text "UL 94V-0" at 11692.84,1745.44 h60
  text "X" at 12367.9,1745.44 h60
  text "RoHS" at 12504.84,1745.44 h60
  text "OTHER" at 13149.24,1745.44 h60
  text "PER ORDER" at 13546.3,1745.44 h60
  text "ADDITIONAL REQUIREMENTS:" at 11202.34,1604.44 h60
  text "MICROSECTION:" at 11277.11,1489.44 h60
  text "YES" at 12182.84,1489.44 h60
  text "REQUIRED" at 13044.34,1333.3 h60
  text "BARE BOARD ELEC. TEST:" at 11277.11,1330.44 h60
  text "NONE" at 12582.84,1330.44 h60
  text "X" at 12917.34,1330.44 h60
  text "PER ORDER" at 13636.34,1330.44 h60
  text "MANUFACTURER'S UL:" at 11277.11,1173.44 h60
  text "RAIL" at 12442.84,1169.15 h60
  text "METAL" at 12934.65,1169.15 h60
  text "X" at 13309.88,1168.8 h60
  text "SILK" at 13446.34,1169.15 h60
  text "VIA`S TO BE TENTED:" at 11256.88,981.8 h60
  text "ALL VIAS ARE NON TENTED VIAS" at 12161.88,981.8 h60
M11 Gerber Information:
  lines w10: -427.12,-964.37 6172.88,-964.37 ; -427.12,-761.03 6174.88,-761.03 ; -427.12,-557.7 -427.12,-1167.7 3577.88,-1167.7 6174.88,-1167.7 6174.88,-557.7 -426.62,-557.7 -426.62,-1167.7 1148.88,-1167.7 ; 2037.88,-1167.7 2037.88,-557.7 ; 3304.88,-761.03 3304.88,-557.7 ; 4144.88,-761.03 4144.88,-557.7 ; 4766.88,-1174.2 4766.88,-971.37
  text "ALL ARTWORK VIEWED FROM TOP SIDE" at -363.62,-689.87 h60
  text "BOARD #:" at 2112.88,-689.87 h60
  text ".PRJ_Number" at 2658.38,-689.87 h60
  text "REV:" at 3502.88,-689.87 h60
  text ".PCB_Rev" at 3794.38,-689.87 h60
  text "SVN REV:" at 4340.88,-689.87 h60
  text ".VersionControl_RevNumber" at 4846.88,-689.87 h60
  text "LAYER NAME =" at -363.62,-892.69 h60
  text "TID #:" at 2112.88,-893.2 h60
  text ".TID" at 2658.38,-893.2 h60
  text "PLOT NAME =" at -363.62,-1098.54 h60
  text ".plot_File_Name" at 441.88,-1098.54 h60
  text "GENERATED    :" at 2114.88,-1098.54 h60
  text ".Print_Date" at 2984.38,-1098.54 h60
  text ".Print_Time" at 3713.38,-1098.54 h60
  text "TEXAS INSTRUMENTS" at 4977.88,-1098.54 h60
M12 Stackup:
  drawing of 191 lines, arcs and shapes, not listed
  text "Layer" at 9598.55,7753.91 h60
  text "Name" at 10008.46,7753.91 h60
  text "Material" at 10938.21,7753.91 h60
  text "Thickness" at 11797.97,7753.91 h60
  text "Constant" at 12447.81,7753.91 h60
  text "Board Layer Stack" at 13017.67,7753.91 h60
  text "1" at 9598.55,7633.91 h60
  text "Top Overlay" at 10008.46,7633.91 h60
  text "2" at 9598.55,7513.91 h60
  text "Top Solder" at 10008.46,7513.91 h60
  text "Solder Resist" at 10938.21,7513.91 h60
  text "0.40mil" at 11797.97,7513.91 h60
  text "3.5" at 12447.81,7513.91 h60
  text "3" at 9598.55,7393.91 h60
  text "Top Layer" at 10008.46,7393.91 h60
  text "Copper" at 10938.21,7393.91 h60
  text "2.80mil" at 11797.97,7393.91 h60
  text "4" at 9598.55,7273.91 h60
  text "Dielectric1" at 10008.46,7273.91 h60
  text "FR-4 High Tg" at 10938.21,7273.91 h60
  text "59.00mil" at 11797.97,7273.91 h60
  text "4.8" at 12447.81,7273.91 h60
  text "5" at 9598.55,7153.91 h60
  text "Bottom Layer" at 10008.46,7153.91 h60
  text "Copper" at 10938.21,7153.91 h60
  text "2.80mil" at 11797.97,7153.91 h60
  text "6" at 9598.55,7033.91 h60
  text "Bottom Solder" at 10008.46,7033.91 h60
  text "Solder Resist" at 10938.21,7033.91 h60
  text "0.40mil" at 11797.97,7033.91 h60
  text "3.5" at 12447.81,7033.91 h60
  text "7" at 9598.55,6913.91 h60
  text "Bottom Overlay" at 10008.46,6913.91 h60
M13 Component Bodies Top:
  text ".Layer_Name" at 441.88,-892.69 h60
M14 Component Bodies Bottom:
  text ".Layer_Name" at 441.88,-892.69 h60
M15 Courtyards Top:
  text ".Layer_Name" at 441.88,-892.69 h60
M16 Courtyards Bottom:
  text ".Layer_Name" at 441.88,-892.69 h60
Drill Drawing:
  lines w10: 7425.11,4348.26 7498.7,4348.26 7498.7,4421.85 7425.11,4421.85 7425.11,4348.26
  lines w15: 7359.43,987.09 9812.93,987.09 ; 7359.43,5126.46 9812.93,5126.46 ; 7784.97,821.51 7784.97,5292.04 ; 8234.64,821.51 8234.64,5292.04 ; 9039.67,821.51 9039.67,5292.04 ; 9369.63,821.51 9369.63,5292.04 ; 7359.43,821.51 9812.93,821.51 9812.93,5292.04 7359.43,5292.04 7359.43,821.51
  text "THIS IS NOT AN IMPEDANCE CONTROL BOARD" at 7372,5407.96 h60
  text "Symbol" at 7458.78,5176.14 h96
  text "Hit Count" at 7834.65,5176.14 h96
  text "Finished Hole Size" at 8284.31,5176.14 h96
  text "Plated" at 9089.35,5176.14 h96
  text "Via/Pad" at 9419.31,5176.14 h96
  text "c" at 7427.38,5012.83 h73.59
  text "83" at 7834.65,5010.56 h80
  text "15.00mil (0.381mm)" at 8284.31,5010.56 h80
  text "PTH" at 9089.35,5010.56 h80
  text "Via" at 9419.31,5010.56 h80
  text "8" at 7834.65,4844.99 h80
  text "25.59mil (0.650mm)" at 8284.31,4844.99 h80
  text "PTH" at 9089.35,4844.99 h80
  text "Pad" at 9419.31,4844.99 h80
  text "O" at 7427.38,4835 h73.59
  text "6" at 7834.65,4679.41 h80
  text "33.47mil (0.850mm)" at 8284.31,4679.41 h80
  text "PTH" at 9089.35,4679.41 h80
  text "Pad" at 9419.31,4679.41 h80
  text "K" at 7427.38,4669.42 h73.59
  text "22" at 7834.65,4513.84 h80
  text "35.43mil (0.900mm)" at 8284.31,4513.84 h80
  text "PTH" at 9089.35,4513.84 h80
  text "Pad" at 9419.31,4513.84 h80
  text "R" at 7427.38,4503.85 h73.59
  text "2" at 7834.65,4348.26 h80
  text "39.37mil (1.000mm)" at 8284.31,4348.26 h80
  text "PTH" at 9089.35,4348.26 h80
  text "Pad" at 9419.31,4348.26 h80
  text "10" at 7834.65,4182.69 h80
  text "39.37mil (1.000mm)" at 8284.31,4182.69 h80
  text "PTH" at 9089.35,4182.69 h80
  text "Pad" at 9419.31,4182.69 h80
  text "N" at 7427.38,4172.7 h73.59
  text "5" at 7834.65,4017.11 h80
  text "40.16mil (1.020mm)" at 8284.31,4017.11 h80
  text "PTH" at 9089.35,4017.11 h80
  text "Pad" at 9419.31,4017.11 h80
  text "M" at 7427.38,4007.12 h73.59
  text "4" at 7834.65,3851.54 h80
  text "41.34mil (1.050mm)" at 8284.31,3851.54 h80
  text "PTH" at 9089.35,3851.54 h80
  text "Pad" at 9419.31,3851.54 h80
  text "S" at 7427.38,3841.55 h73.59
  text "2" at 7834.65,3685.96 h80
  text "41.50mil (1.054mm)" at 8284.31,3685.96 h80
  text "PTH" at 9089.35,3685.96 h80
  text "Pad" at 9419.31,3685.96 h80
  text "V" at 7427.38,3675.97 h73.59
  text "2" at 7834.65,3520.39 h80
  text "43.31mil (1.100mm)" at 8284.31,3520.39 h80
  text "PTH" at 9089.35,3520.39 h80
  text "Pad" at 9419.31,3520.39 h80
  text "]" at 7439.64,3510.4 h73.59
  text "1" at 7834.65,3354.81 h80
  text "45.28mil (1.150mm)" at 8284.31,3354.81 h80
  text "PTH" at 9089.35,3354.81 h80
  text "Pad" at 9419.31,3354.81 h80
  text "L" at 7427.38,3344.82 h73.59
  text "6" at 7834.65,3189.24 h80
  text "45.63mil (1.159mm)" at 8284.31,3189.24 h80
  text "PTH" at 9089.35,3189.24 h80
  text "Pad" at 9419.31,3189.24 h80
  text "W" at 7427.38,3179.25 h73.59
  text "7" at 7834.65,3023.66 h80
  text "45.63mil (1.159mm)" at 8284.31,3023.66 h80
  text "PTH" at 9089.35,3023.66 h80
  text "Pad" at 9419.31,3023.66 h80
  text "X" at 7427.38,3013.67 h73.59
  text "a" at 7427.38,2860.36 h73.59
  text "6" at 7834.65,2858.09 h80
  text "46.18mil (1.173mm)" at 8284.31,2858.09 h80
  text "PTH" at 9089.35,2858.09 h80
  text "Pad" at 9419.31,2858.09 h80
  text "2" at 7834.65,2692.51 h80
  text "46.19mil (1.173mm)" at 8284.31,2692.51 h80
  text "PTH" at 9089.35,2692.51 h80
  text "Pad" at 9419.31,2692.51 h80
  text "b" at 7427.38,2682.52 h73.59
  text "^" at 7427.38,2541.47 h73.59
  text "2" at 7834.65,2526.94 h80
  text "49.37mil (1.254mm)" at 8284.31,2526.94 h80
  text "PTH" at 9089.35,2526.94 h80
  text "Pad" at 9419.31,2526.94 h80
  text "12" at 7834.65,2361.36 h80
  text "50.00mil (1.270mm)" at 8284.31,2361.36 h80
  text "PTH" at 9089.35,2361.36 h80
  text "Pad" at 9419.31,2361.36 h80
  text "T" at 7427.38,2351.37 h73.59
  text "4" at 7834.65,2195.79 h80
  text "55.12mil (1.400mm)" at 8284.31,2195.79 h80
  text "PTH" at 9089.35,2195.79 h80
  text "Pad" at 9419.31,2195.79 h80
  text "U" at 7427.38,2185.8 h73.59
  text "`" at 7439.64,2044.75 h73.59
  text "4" at 7834.65,2030.21 h80
  text "59.06mil (1.500mm)" at 8284.31,2030.21 h80
  text "PTH" at 9089.35,2030.21 h80
  text "Pad" at 9419.31,2030.21 h80
  text "_" at 7427.38,1891.43 h73.59
  text "8" at 7834.65,1864.64 h80
  text "62.99mil (1.600mm)" at 8284.31,1864.64 h80
  text "PTH" at 9089.35,1864.64 h80
  text "Pad" at 9419.31,1864.64 h80
  text "3" at 7834.65,1699.06 h80
  text "70.08mil (1.780mm)" at 8284.31,1699.06 h80
  text "PTH" at 9089.35,1699.06 h80
  text "Pad" at 9419.31,1699.06 h80
  text "[" at 7439.64,1689.07 h73.59
  text "2" at 7834.65,1533.49 h80
  text "78.74mil (2.000mm)" at 8284.31,1533.49 h80
  text "PTH" at 9089.35,1533.49 h80
  text "Pad" at 9419.31,1533.49 h80
  text "Y" at 7427.38,1523.5 h73.59
  text "16" at 7834.65,1367.91 h80
  text "80.00mil (2.032mm)" at 8284.31,1367.91 h80
  text "PTH" at 9089.35,1367.91 h80
  text "Pad" at 9419.31,1367.91 h80
  text "Q" at 7427.38,1357.92 h73.59
  text "2" at 7834.65,1202.34 h80
  text "98.43mil (2.500mm)" at 8284.31,1202.34 h80
  text "PTH" at 9089.35,1202.34 h80
  text "Pad" at 9419.31,1202.34 h80
  text "P" at 7427.38,1192.35 h73.59
  text "2" at 7834.65,1036.76 h80
  text "100.39mil (2.550mm)" at 8284.31,1036.76 h80
  text "PTH" at 9089.35,1036.76 h80
  text "Pad" at 9419.31,1036.76 h80
  text "Z" at 7427.38,1026.77 h73.59
  text "221 Total" at 7834.65,871.19 h80
  text "TOLERANCE:" at 7955,542.33 h60
  text "FOR 15MIL DRILL +0/-15MIL" at 7972.93,412.2 h60
  text "FOR PTH DRILL +/-3MIL" at 7972.93,304.2 h60
  text ".Layer_Name" at 441.88,-892.69 h60
M17 Embedded Cavity:
  text ".Layer_Name" at 441.88,-892.69 h60
M18 Embedded Assembly:
  text ".Layer_Name" at 441.88,-892.69 h60
M19 Embedded Keepout:
  text ".Layer_Name" at 441.88,-892.69 h60

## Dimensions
0,3149.61 to 0,0 on M2 Board Dimensions
0,0 to 6299.21,0 on M2 Board Dimensions
-135.12,-434.2 to 864.88,-434.2 on M2 Board Dimensions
